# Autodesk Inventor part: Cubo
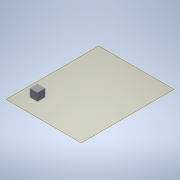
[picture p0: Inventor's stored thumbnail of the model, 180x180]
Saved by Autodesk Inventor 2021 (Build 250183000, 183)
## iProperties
Created: 2021-02
Part Number: Cubo
Material: Genérico
Document SubType Name: Modeling
Designer: ATOUZA
Density: 1 g/cm^3
Appearance: Valor por defecto
Author: ATOUZA
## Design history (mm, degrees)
node "Plano de trabajo1"
sketch "Boceto1"
  geometry: L1 (66.361, 317.851)-(101.361, 317.851); L2 (101.361, 317.851)-(101.361, 282.851); L3 (101.361, 282.851)-(66.361, 282.851); L4 (66.361, 282.851)-(66.361, 317.851); 1 further point
  constraints: 8 end point, 2 parallel, 1 horizontal, 1 perpendicular
  dimensions: "d0" = 35 distance of L2.end L3.end; "d1" = 35 distance of L1.end L2.end
extrude "Extrusión1" new body sketch "Boceto1" distance "d2" = 35; taper "d3" = 0 deg
node "Sólido1"
